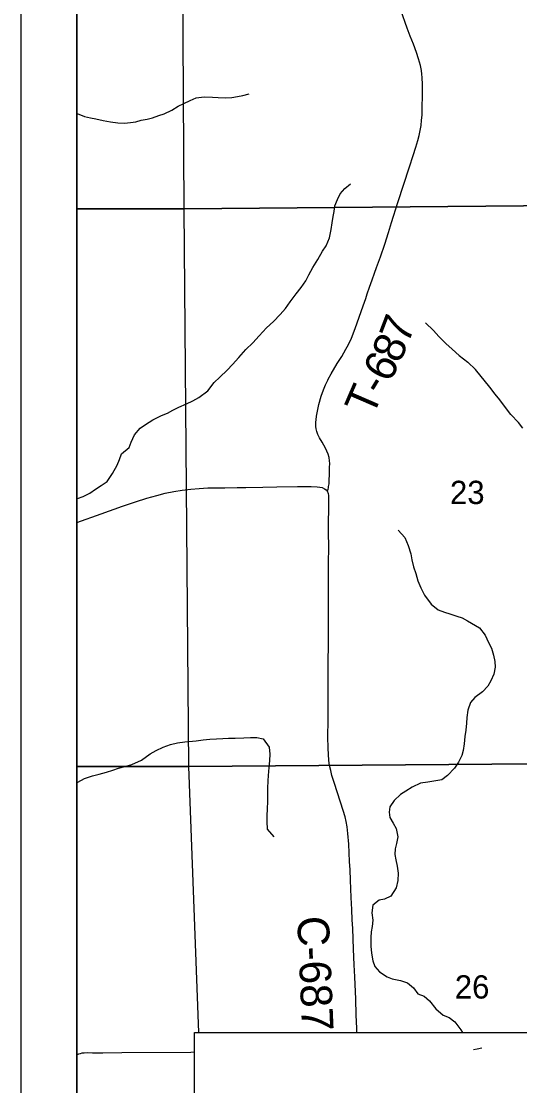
# Model space of a CAD drawing. Extents: x 0 to 34, y 0 to 22.
# Drawn here: x 1.76 to 2.657, y 18.172 to 20.086 of the extents above; entities that cross this region are included whole.
import ezdxf

# ---------------------------------------------------------------- set-up
doc = ezdxf.new("R2010")
doc.units = 0
for name, color, linetype in [('GM_X_County_Road_Text', 7, 'Continuous'), ('GM_X_Interchange_Ramps', 7, 'Continuous'), ('GM_X_Section_Text', 7, 'Continuous'), ('GM_X_State_Location', 7, 'Continuous'), ('GM_X_State_Route', 7, 'Continuous'), ('GM_X_Township_Road', 7, 'Continuous'), ('GM_X_Township_Text', 7, 'Continuous'), ('SH_Data', 7, 'Continuous'), ('SH_Text', 7, 'Continuous')]:
    doc.layers.add(name, color=color, linetype=linetype)

msp = doc.modelspace()

# ---------------------------------------------------------------- linework, layer by layer
at = {"layer": 'GM_X_County_Road_Text'}
for points in [[(1.8602, 19.9199), (1.8635, 19.9187), (1.8741, 19.9149), (1.8847, 19.9126), (1.8946, 19.9103), (1.9075, 19.9073), (1.9208, 19.905), (1.9337, 19.9035), (1.9462, 19.9027), (1.9565, 19.9042), (1.9663, 19.9054), (1.9758, 19.908), (1.9865, 19.9099), (1.9963, 19.9126), (2.0077, 19.9168), (2.0172, 19.9198), (2.0309, 19.9259), (2.0427, 19.9331), (2.0529, 19.938), (2.0639, 19.9433), (2.0746, 19.9482), (2.089, 19.9501), (2.1042, 19.9497), (2.1144, 19.949), (2.1273, 19.9486), (2.1391, 19.949), (2.1493, 19.9505), (2.1588, 19.9528), (2.1702, 19.9558)], [(2.2358, 19.5696), (2.2442, 19.5813), (2.2545, 19.5958), (2.2636, 19.6075), (2.2719, 19.6193), (2.2777, 19.6303), (2.2845, 19.6432), (2.2936, 19.6576), (2.302, 19.6724), (2.3085, 19.6823), (2.3146, 19.6967), (2.3176, 19.7115), (2.3195, 19.7233), (2.3214, 19.7347), (2.323, 19.7442), (2.3245, 19.7541), (2.3291, 19.7658), (2.334, 19.7757), (2.3424, 19.7852), (2.3522, 19.7936)], [(1.8602, 19.2275), (1.8615, 19.228), (1.8714, 19.2314), (1.8836, 19.2375), (1.8938, 19.2447), (1.9041, 19.2511), (1.9147, 19.2587), (1.9246, 19.2728), (1.933, 19.2876), (1.9372, 19.2982), (1.9406, 19.3081), (1.9546, 19.3198), (1.9577, 19.3293), (1.9638, 19.3422), (1.974, 19.3544), (1.9835, 19.3608), (1.9968, 19.3692), (2.0124, 19.3771), (2.023, 19.3813), (2.0329, 19.387), (2.0439, 19.3923), (2.0576, 19.398), (2.069, 19.4033), (2.0796, 19.4094), (2.0956, 19.4212), (2.1074, 19.4363), (2.1173, 19.4458), (2.1309, 19.4587), (2.1401, 19.4686), (2.1515, 19.4815), (2.1644, 19.4956), (2.1769, 19.5077), (2.1879, 19.5206), (2.2016, 19.5346), (2.2138, 19.546), (2.2259, 19.5586), (2.2358, 19.5696)], [(2.4875, 19.544), (2.5015, 19.5299), (2.5113, 19.5189), (2.5239, 19.5064), (2.5352, 19.4965), (2.5481, 19.4851), (2.5633, 19.473), (2.5773, 19.46)], [(2.6624, 19.3542), (2.6544, 19.3644), (2.6411, 19.3792), (2.6296, 19.3939), (2.6209, 19.4053), (2.6129, 19.4155), (2.603, 19.428), (2.5773, 19.46)], [(2.4381, 19.1708), (2.4502, 19.1575), (2.4563, 19.1434), (2.4608, 19.1286), (2.4631, 19.1176), (2.4657, 19.105), (2.4702, 19.0929), (2.4736, 19.0796), (2.4789, 19.0671), (2.4854, 19.0541), (2.4975, 19.0378), (2.5104, 19.0279), (2.5218, 19.0234), (2.5313, 19.0203), (2.5438, 19.0165), (2.5533, 19.0131), (2.5628, 19.0078), (2.5843, 18.9953)], [(2.5843, 18.9953), (2.5946, 18.9824), (2.6007, 18.9692), (2.6061, 18.9586), (2.6099, 18.9461), (2.6123, 18.9347), (2.6127, 18.9245), (2.6101, 18.9119), (2.6052, 18.9001), (2.5996, 18.8906), (2.5901, 18.88), (2.5763, 18.8703)], [(2.5763, 18.8703), (2.5683, 18.8608), (2.5637, 18.8472), (2.5618, 18.8342), (2.561, 18.8236), (2.5599, 18.8111), (2.5583, 18.8001), (2.5572, 18.7868), (2.5553, 18.775), (2.553, 18.7655), (2.5469, 18.7538), (2.5397, 18.7427), (2.5271, 18.7298), (2.5169, 18.7222), (2.5062, 18.72), (2.4914, 18.7181), (2.4785, 18.7158), (2.4633, 18.7086), (2.4519, 18.7018), (2.4424, 18.6957), (2.431, 18.6851), (2.4234, 18.6737), (2.4219, 18.6638), (2.423, 18.6543), (2.4295, 18.6441), (2.4348, 18.6342), (2.4374, 18.6194), (2.4351, 18.6076), (2.4328, 18.5977), (2.4325, 18.5875), (2.434, 18.578), (2.4366, 18.5666), (2.4385, 18.5541), (2.4377, 18.5412), (2.4347, 18.5279), (2.4248, 18.5127), (2.4134, 18.5074), (2.4039, 18.5059), (2.3925, 18.4967), (2.3906, 18.4831), (2.3925, 18.4694), (2.3913, 18.458), (2.3898, 18.4485), (2.389, 18.4383), (2.389, 18.4231), (2.3905, 18.4102), (2.3928, 18.3965), (2.3962, 18.3866), (2.4045, 18.3767), (2.4182, 18.368), (2.4276, 18.3642), (2.4424, 18.3612), (2.455, 18.357), (2.4656, 18.3479), (2.4739, 18.3372), (2.4849, 18.3327), (2.4948, 18.3247), (2.5058, 18.3102), (2.5194, 18.2988), (2.5297, 18.2947), (2.5399, 18.2871), (2.5509, 18.2722), (2.5542, 18.2679)], [(1.8602, 18.7171), (1.8617, 18.718), (1.8739, 18.7241), (1.8883, 18.729), (1.9004, 18.7324), (1.9137, 18.7358), (1.9247, 18.7396), (1.9354, 18.743), (1.949, 18.7464), (1.9593, 18.7495), (1.9764, 18.7571), (1.992, 18.7688), (2.0026, 18.7749), (2.0155, 18.781), (2.0284, 18.7855), (2.0413, 18.7885), (2.0542, 18.7904), (2.0747, 18.7923), (2.0873, 18.7938), (2.0994, 18.795), (2.1116, 18.7957), (2.1226, 18.7965), (2.1332, 18.7969), (2.1453, 18.7968), (2.1605, 18.7976), (2.1727, 18.798), (2.1837, 18.798), (2.1955, 18.7957), (2.2061, 18.7809), (2.2076, 18.768), (2.2068, 18.7566), (2.2056, 18.7444), (2.2045, 18.73), (2.2037, 18.7201), (2.2033, 18.7072), (2.2033, 18.6954), (2.2029, 18.6829), (2.2025, 18.67), (2.2017, 18.6575), (2.2017, 18.6468), (2.2025, 18.6335), (2.2146, 18.6195)]]:
    msp.add_lwpolyline(points, dxfattribs=at)
at = {"layer": 'GM_X_Interchange_Ramps'}
for points in [[(2.3125, 19.4426), (2.3175, 19.4519), (2.3285, 19.4704), (2.337, 19.4834), (2.3442, 19.4965), (2.3488, 19.505), (2.3544, 19.5164), (2.3606, 19.5334), (2.368, 19.5537), (2.3755, 19.5742), (2.38, 19.5873), (2.3827, 19.5962), (2.3865, 19.6079), (2.3915, 19.6211), (2.3956, 19.6329), (2.3991, 19.6431), (2.4062, 19.6623), (2.414, 19.6855), (2.4208, 19.7064), (2.4264, 19.7244), (2.4376, 19.7599), (2.4587, 19.8243), (2.4655, 19.8449), (2.4702, 19.8597), (2.4737, 19.8716), (2.4761, 19.8805), (2.478, 19.8896), (2.4795, 19.8988), (2.4805, 19.908), (2.4812, 19.9172), (2.4815, 19.9263), (2.4818, 19.9571), (2.4819, 19.9726), (2.4816, 19.985), (2.4811, 19.9912), (2.4802, 19.9973), (2.4782, 20.0064), (2.475, 20.0183), (2.4711, 20.0301), (2.4656, 20.0446), (2.4599, 20.059), (2.4545, 20.0735), (2.443, 20.1057)], [(2.3109, 19.2407), (2.3116, 19.243), (2.3121, 19.2446), (2.3127, 19.2473), (2.3132, 19.2496), (2.3136, 19.2521), (2.3139, 19.2543), (2.3143, 19.2594), (2.3145, 19.2724), (2.3148, 19.2836), (2.3151, 19.2907), (2.3148, 19.2954), (2.3139, 19.3015), (2.3124, 19.3074), (2.3102, 19.3131), (2.3075, 19.3186), (2.3013, 19.3291), (2.2966, 19.3371), (2.2939, 19.3427), (2.2917, 19.3484), (2.2908, 19.3531), (2.2903, 19.3574), (2.2903, 19.361), (2.2903, 19.3649), (2.2907, 19.3695), (2.2916, 19.376), (2.2932, 19.3847), (2.2955, 19.3969), (2.2997, 19.4119), (2.3037, 19.4234), (2.3075, 19.4324), (2.3115, 19.4408), (2.3125, 19.4426)], [(1.8602, 18.2277), (1.8611, 18.2281), (1.864, 18.2293), (1.867, 18.2302), (1.87, 18.2309), (1.8731, 18.2313), (1.8793, 18.2316), (1.8886, 18.2314), (1.9072, 18.2313), (1.9414, 18.2318), (2.0655, 18.2326), (2.0719, 18.2327)], [(2.574, 18.2371), (2.5805, 18.2385), (2.5885, 18.2398)]]:
    msp.add_lwpolyline(points, dxfattribs=at)
at = {"layer": 'GM_X_State_Route'}
for points in [[(1.8602, 20.776), (1.8602, 19.7485), (2.0531, 19.7487), (2.0472, 20.7772)], [(2.0472, 20.7772), (3.0692, 20.7682), (3.0705, 19.7579), (2.0531, 19.7487)], [(2.0531, 19.7487), (3.0705, 19.7579), (3.0743, 18.754), (2.0616, 18.746)], [(1.8602, 19.7485), (1.8602, 18.7459), (2.0616, 18.746), (2.0531, 19.7487)]]:
    msp.add_lwpolyline(points, close=True, dxfattribs=at)
for points in [[(2.0795, 18.2679), (2.0616, 18.746), (1.8602, 18.7459), (1.8602, 17.7252), (2.0719, 17.7249)], [(2.0795, 18.2679), (2.0616, 18.746), (3.0743, 18.754), (3.0806, 18.2679)]]:
    msp.add_lwpolyline(points, dxfattribs=at)
at = {"layer": 'GM_X_Township_Road'}
for points in [[(1.8602, 19.1848), (1.9037, 19.2004), (1.9422, 19.214), (1.9657, 19.222), (1.9864, 19.2285), (2.0043, 19.2335), (2.0193, 19.2372), (2.0344, 19.2404), (2.0496, 19.2429), (2.065, 19.2448), (2.0804, 19.2461), (2.0958, 19.2468), (2.1267, 19.2472), (2.1484, 19.2474), (2.1639, 19.2476), (2.195, 19.2482), (2.2198, 19.2489), (2.257, 19.2492), (2.2818, 19.2492), (2.2927, 19.2488), (2.2972, 19.2484), (2.3016, 19.2475), (2.3055, 19.2455), (2.3085, 19.2434), (2.3109, 19.2407)], [(2.3641, 18.2679), (2.3636, 18.2746), (2.3627, 18.2995), (2.3619, 18.3274), (2.3601, 18.3678), (2.3592, 18.3895), (2.3579, 18.4174), (2.3565, 18.4545), (2.3556, 18.47), (2.3546, 18.4886), (2.3537, 18.5104), (2.3531, 18.5259), (2.3524, 18.5413), (2.3517, 18.5599), (2.3509, 18.5754), (2.3493, 18.6064), (2.3479, 18.6255), (2.3463, 18.6374), (2.3447, 18.6472), (2.3428, 18.6556), (2.3393, 18.6671), (2.3347, 18.6821), (2.3229, 18.717), (2.3192, 18.7299), (2.3169, 18.7387), (2.315, 18.7477), (2.3136, 18.7566), (2.3129, 18.7681), (2.3123, 18.7785), (2.312, 18.8001), (2.3126, 18.8284), (2.3126, 18.9246), (2.3129, 18.9743), (2.3129, 19.0054), (2.3129, 19.0705), (2.313, 19.0921), (2.3132, 19.1106), (2.3134, 19.1413), (2.3132, 19.166), (2.3136, 19.228), (2.3133, 19.2338), (2.3128, 19.2361), (2.3121, 19.2383), (2.3109, 19.2407)]]:
    msp.add_lwpolyline(points, dxfattribs=at)
at = {"layer": 'SH_Data'}
for points in [[(1.7602, 21.2866), (8.7602, 21.2866), (8.7602, 14.2866), (1.7602, 14.2866)], [(1.8602, 21.1866), (8.6602, 21.1866), (8.6602, 14.3866), (1.8602, 14.3866)]]:
    msp.add_lwpolyline(points, close=True, dxfattribs=at)
at = {"layer": 'SH_Text'}
for p, q in [((2.0719, 17.4855), (2.0719, 18.2679)), ((2.0719, 18.2679), (4.4056, 18.2679))]:
    msp.add_line(p, q, dxfattribs=at)

# ---------------------------------------------------------------- texts
at = {"layer": 'GM_X_Section_Text'}
msp.add_text('C-687', height=0.05682, rotation=272.4771, dxfattribs=at).set_placement((2.2565, 18.476))
at = {"layer": 'GM_X_State_Location'}
for s, p in [('23', (2.5314, 19.2179)), ('26', (2.5401, 18.3287))]:
    msp.add_text(s, height=0.04186, rotation=0, dxfattribs=at).set_placement(p)
at = {"layer": 'GM_X_Township_Text'}
for s, rotation, p in [('7', 69.0962, (2.4557, 19.5038)), ('8', 66.5658, (2.4407, 19.4691)), ('6', 62.5399, (2.4227, 19.4342)), ('T', 66.6258, (2.3925, 19.3733)), ('-', 58.4927, (2.4084, 19.4105))]:
    msp.add_text(s, height=0.0568, rotation=rotation, dxfattribs=at).set_placement(p)

doc.saveas('drawing.dxf')
